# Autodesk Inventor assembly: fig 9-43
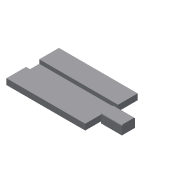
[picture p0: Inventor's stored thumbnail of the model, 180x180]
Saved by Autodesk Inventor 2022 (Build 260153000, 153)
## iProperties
Created: 2013-07
Part Number: fig 9-43
Document SubType Name: Assembly
Designer: CADCIM
Author: CADCIM
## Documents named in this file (3)
- D:\PROJECTS_2021\Resources\Part Files\c09_Inv_2022_prt\fig 9-44.iam
- D:\PROJECTS_2021\Resources\Part Files\c09_Inv_2022_prt\15.ipt
- D:\PROJECTS_2021\Resources\Part Files\c09_Inv_2022_prt\16.ipt
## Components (2 placed, 2 different names)
1. 15:1
2. 16:1
